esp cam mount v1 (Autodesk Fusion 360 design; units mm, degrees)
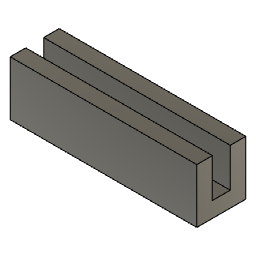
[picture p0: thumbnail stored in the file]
sketch "Sketch1" plane through (0, 0, 0) normal (0, 0, 1) x axis (1, 0, 0)
  line L1 (-12, -3.15) -> (12, -3.15)
  line L2 (-12, 3.15) -> (-12, -3.15)
  line L3 (12, 3.15) -> (-12, 3.15)
  line L4 (12, -3.15) -> (12, 3.15)
  line L5 (-12, 3.15) -> (12, -3.15)
  line L6 (12, 3.15) -> (-12, -3.15)
  point P6 (0, 0)
  point P1 (0, 0)
  point P3 (-12, -3.15)
  point P4 (-12, 3.15)
  point P5 (12, 3.15)
  perpendicular L1 L2
  parallel L1 L3
  parallel L2 L4
  horizontal L1
  coincident L5 P6
  coincident L6 P6
  coincident P1 P6
  dimension "d1" distance P3 P4 = 6.3
  dimension "d2" distance P4 P5 = 24
extrude "Extrude1" new body sketch "Sketch1" profile of L1 L2 L3 L4 along normal blind 2
sketch "Sketch2" plane through (0, 0, 2) normal (0, 0, 1) x axis (-1, 0, 0)
  line L1 (12, -3.15) -> (-12, -3.15)
  line L2 (12, 3.15) -> (12, -3.15)
  line L3 (-12, 3.15) -> (12, 3.15)
  line L4 (-12, -3.15) -> (-12, 3.15)
  line L5 (-12, 3.15) -> (12, 3.15)
  line L6 (-12, 1.15) -> (-12, 3.15)
  line L7 (12, 1.15) -> (-12, 1.15)
  line L8 (12, 3.15) -> (12, 1.15)
  point P8 (-12, 1.15)
  point P4 (12, 3.15)
  point P6 (12, 3.15)
  horizontal L5
  vertical L6
  horizontal L7
  vertical L8
  coincident L4 P8
  coincident P4 P6
  dimension "d5" distance L5 L7 = 2
extrude "Extrude2" add sketch "Sketch2" profile of L2 L3 L4 L5 L6 L7 L8 along normal blind 5
mirror "Mirror1"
